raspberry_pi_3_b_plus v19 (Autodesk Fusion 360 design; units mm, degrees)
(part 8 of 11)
sketch "Sketch5" plane through (0, 0, 13.6) normal (0, 0, 1) x axis (-1, 0, 0)
  line L1 (-7.9893, 23.6893) -> (-7.9893, 10.7893)
  line L2 (-16.3393, 23.6893) -> (-7.9893, 23.6893)
  line L3 (-16.3393, 10.7893) -> (-16.3393, 23.6893)
  line L4 (-7.9893, 10.7893) -> (-16.3393, 10.7893)
  line L5 (-19.3393, 13.7893) -> (-16.3393, 10.7893)
  line L6 (-24.4893, 13.7893) -> (-19.3393, 13.7893)
  line L7 (-23.4893, 23.6893) -> (-23.4893, 22.3393)
  line L8 (0, 31.7433) -> (0, 0)
  line L9 (16.3393, 23.6893) -> (16.3393, 10.7893)
  line L10 (-24.4893, 22.3393) -> (-23.4893, 22.3393)
  line L11 (-24.4893, 13.7893) -> (-24.4893, 22.3393)
  line L12 (-22.3143, 26.1643) -> (-22.3143, 23.6893)
  line L13 (-20.9643, 23.8403) -> (-20.9643, 26.1643)
  line L14 (-16.5643, 23.8403) -> (-20.5643, 23.8403)
  line L15 (-16.5643, 23.6893) -> (-16.5643, 23.8403)
  line L16 (-22.3143, 23.6893) -> (-23.4893, 23.6893)
  line L17 (-16.3393, 23.6893) -> (-16.5643, 23.6893)
  line L18 (16.3393, 23.6893) -> (16.5643, 23.6893)
  line L19 (16.5643, 23.6893) -> (16.5643, 23.8403)
  line L20 (16.5643, 23.8403) -> (20.5643, 23.8403)
  line L21 (20.9643, 23.8403) -> (20.9643, 26.1643)
  line L22 (22.3143, 26.1643) -> (22.3143, 23.6893)
  line L23 (22.3143, 23.6893) -> (23.4893, 23.6893)
  line L24 (23.4893, 23.6893) -> (23.4893, 22.3393)
  line L25 (24.4893, 22.3393) -> (23.4893, 22.3393)
  line L26 (24.4893, 13.7893) -> (24.4893, 22.3393)
  line L27 (24.4893, 13.7893) -> (19.3393, 13.7893)
  line L28 (19.3393, 13.7893) -> (16.3393, 10.7893)
  arc A1 centre (-21.6393, 26.1643) radius 0.675 clockwise from (-22.3143, 26.1643) to (-20.9643, 26.1643)
  arc A2 centre (-20.7643, 23.8403) radius 0.2 clockwise from (-20.5643, 23.8403) to (-20.9643, 23.8403)
  arc A3 centre (20.7643, 23.8403) radius 0.2 clockwise from (20.9643, 23.8403) to (20.5643, 23.8403)
  arc A4 centre (21.6393, 26.1643) radius 0.675 clockwise from (20.9643, 26.1643) to (22.3143, 26.1643)
  point P5 (-16.3393, 10.7893)
  point P6 (-16.3393, 10.7893)
  point P4 (-16.3393, 23.6893)
  point P9 (-16.3393, 23.6893)
  point P1 (0, 0)
  point P10 (0, 0)
  point P22 (-21.6393, 26.8393)
  point P27 (-16.5643, 23.6893)
  point P44 (16.3393, 10.7893)
  point P7 (-19.3393, 13.7893)
  point P43 (19.3393, 13.7893)
  point P8 (-23.4893, 23.6893)
  point P39 (23.4893, 23.6893)
  point P29 (16.3393, 23.6893)
  point P14 (-23.4893, 22.3393)
  point P40 (23.4893, 22.3393)
  point P15 (-24.4893, 22.3393)
  point P41 (24.4893, 22.3393)
  point P16 (-24.4893, 13.7893)
  point P42 (24.4893, 13.7893)
  point P17 (-22.3143, 23.6893)
  point P38 (22.3143, 23.6893)
  point P18 (-22.3143, 26.1643)
  point P37 (22.3143, 26.1643)
  point P19 (-20.9643, 26.1643)
  point P35 (20.9643, 26.1643)
  point P21 (-20.9643, 23.8403)
  point P34 (20.9643, 23.8403)
  point P23 (-20.5643, 23.8403)
  point P32 (20.5643, 23.8403)
  point P25 (-20.5643, 23.8403)
  point P31 (20.5643, 23.8403)
  point P26 (-16.5643, 23.8403)
  point P30 (16.5643, 23.8403)
  point P28 (16.5643, 23.6893)
  point P24 (-20.7643, 23.8403)
  point P3 (-7.9893, 23.6893)
  point P20 (-21.6393, 26.1643)
  coincident P5 P6
  coincident P4 P9
  horizontal L16
  horizontal L6
  vertical L7
  coincident P1 P10
  vertical L8
  horizontal L10
  vertical L11
  tangent L12 A1
  vertical L13
  vertical L12
  tangent A1 L13
  midpoint A1 P22
  tangent L13 A2
  coincident P27 L16
  perpendicular L15 L16
  collinear L16 L17
  symmetric P6 L8 P44
  symmetric P7 L8 P43
  symmetric P8 L8 P39
  symmetric P9 L8 P29
  symmetric L8 P14 P40
  symmetric L8 P15 P41
  symmetric L8 P16 P42
  symmetric L8 P17 P38
  symmetric L8 P18 P37
  symmetric L8 P19 P35
  symmetric L8 A1 A4
  symmetric L8 P21 P34
  symmetric L8 P23 P32
  symmetric L8 A2 A3
  symmetric L8 P25 P31
  symmetric L8 P26 P30
  symmetric L8 P27 P28
  coincident P23 P25
  coincident P24 L14
  coincident P31 P32
  dimension "d32_6" angle L5 L6 = 45
  dimension "d33_6" distance L4 L6 = 3
  dimension "d46_5" distance L10 L16 = 1.35
  dimension "d47_4" distance L1 L11 = 16.5
  dimension "d54_7" radius A1 = 0.675 (= "1.35 mm / 2")
  dimension "d55_6" distance P22 L16 = 3.15 (= "3 mm + d1_5")
  dimension "d56_6" distance P3 P20 = 13.65 (= "10.75 mm + 3.05 mm - d1_5")
  dimension "d57_6" distance L7 L11 = 1
  dimension "d59_4" radius A2 = 0.2
  dimension "d60_4" distance L14 L16 = 0.151 (= "d1_5 + 0.001 mm")
  dimension "d145_2" distance P23 L15 = 4
extrude "Extrude4" add sketch "Sketch5" profile of L3 L5 L6 L7 L17 L9 L10 L11 L12 A1 L13 A2 L14 L15 L18 L19 L20 A3 L21 A4 L22 L23 L24 L25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 to an object
work_plane "WorkPlane2" AlongDistance -23.739 named "d150_1"
step "Refold1"
face "EdgeFlange7" FlangeHeight 0.25 named "d42_6" FlangeAngle 45 named "d43_5"
face "EdgeFlange8" FlangeHeight 4 named "d44_8" FlangeAngle 45 named "d45_5"
face "EdgeFlange10" FlangeHeight 1 named "d61_5" FlangeAngle 90 named "d62_4"
sketch "Sketch6" plane through (7.95, 0, 0) normal (1, 0, 0) x axis (0, 1, 0)
  line L1 (10.3, 13.1939) -> (10.3, 1.35)
  line L2 (7.45, 10.3439) -> (10.3, 13.1939)
  line L3 (7.45, 1.35) -> (7.45, 10.3439)
  line L4 (10.3, 1.35) -> (7.45, 1.35)
  line L5 (9.35, 3.65) -> (8.35, 3.65)
  line L6 (9.35, 2.5) -> (9.35, 3.65)
  line L7 (8.35, 2.5) -> (9.35, 2.5)
  line L8 (8.35, 3.65) -> (8.35, 2.5)
  point P6 (8.35, 3.65)
  point P7 (9.35, 3.65)
  point P9 (8.35, 2.5)
  point P1 (0, 0)
  point P8 (9.35, 2.5)
  point P10 (10.6, 1.35)
  horizontal L5
  vertical L6
  horizontal L7
  vertical L8
  dimension "d63_6" distance P6 P7 = 1
  dimension "d64_6" distance P6 P9 = 1.15
  dimension "d65_6" distance P1 P8 = 2.5
  dimension "d66_5" distance L6 P10 = 1.25
extrude "Extrude5" cut sketch "Sketch6" profile of L5 L6 L7 L8 no distance stored
face "EdgeFlange11" FlangeHeight 0.95 named "d68_6" FlangeAngle 10 named "d69_7" BendWidth 0.05 named "d70_3" BendDepth 0 named "d71_2" BendRemnant 0.3 named "d72_4"
work_plane "WorkPlane1" AlongDistance -10.45 (= "-( 10.75 mm - 2 * d1_5 )") named "d87_4"
sketch "Sketch2" plane through (0, -10.45, 0) normal (0, 1, 0) x axis (1, 0, 0)
  line L1 (7.8, -0.37) -> (-7.8, -0.37)
  line L2 (-6.915, -1.07) -> (-3.725, -1.07)
  line L3 (7.8, -13.37) -> (7.8, -0.37)
  line L4 (5.95, -10.87) -> (-5.95, -10.87)
  line L5 (5.95, -8.37) -> (5.95, -10.87)
  line L6 (-6.915, -3.33) -> (-6.915, -1.07)
  line L7 (-3.725, -3.33) -> (-6.915, -3.33)
  line L8 (6.95, -8.37) -> (5.95, -8.37)
  line L9 (-7.8, -0.37) -> (-7.8, -13.37)
  line L10 (-7.8, -13.37) -> (7.8, -13.37)
  line L11 (-3.725, -3.33) -> (-3.725, -1.07)
  line L12 (2.03, -0.97) -> (2.03, -2.31)
  line L13 (3.725, -3.33) -> (3.725, -1.07)
  line L14 (-3.15, -0.97) -> (3.15, -0.97)
  line L15 (6.95, -5.37) -> (6.95, -8.37)
  line L16 (-6.95, -8.37) -> (-6.95, -5.37)
  line L17 (3.725, -1.07) -> (6.915, -1.07)
  line L18 (5.955, -5.37) -> (6.95, -5.37)
  line L19 (-6.95, -5.37) -> (-5.955, -5.37)
  line L20 (-5.95, -8.37) -> (-6.95, -8.37)
  line L21 (6.915, -3.33) -> (3.725, -3.33)
  line L22 (-5.95, -10.87) -> (-5.95, -8.37)
  line L23 (6.915, -1.07) -> (6.915, -3.33)
  line L24 (-2.03, -2.31) -> (-2.03, -0.97)
  line L25 (0, -15.0494) -> (0, 0)
  line L26 (-5.955, -4.13) -> (-5.955, -5.37)
  line L27 (-5.955, -4.13) -> (-3.15, -4.13)
  line L28 (-3.15, -0.97) -> (-3.15, -4.13)
  line L29 (-3.15, -2.31) -> (-2.03, -2.31)
  line L30 (5.955, -4.13) -> (5.955, -5.37)
  line L31 (3.15, -4.13) -> (5.955, -4.13)
  line L32 (3.15, -0.97) -> (3.15, -4.13)
  line L33 (2.03, -2.31) -> (3.15, -2.31)
  line L34 (-5.955, -5.37) -> (-5.95, -8.37)
  line L35 (5.955, -5.37) -> (5.95, -8.37)
  line L36 (5.9525, -6.87) -> (-5.9525, -6.87)
  line L37 (-6.915, -1.07) -> (-3.725, -3.33)
  line L38 (-3.725, -1.07) -> (-6.915, -3.33)
  line L39 (3.725, -1.07) -> (6.915, -3.33)
  line L40 (6.915, -1.07) -> (3.725, -3.33)
  point P1 (0, 0)
  point P26 (0, 0)
  point P20 (-7.8, -0.37)
  point P23 (7.8, -0.37)
  point P5 (-5.95, -10.87)
  point P6 (5.95, -10.87)
  point P28 (-6.95, -6.87)
  point P8 (-6.95, -8.37)
  point P17 (6.95, -8.37)
  point P3 (-6.95, -5.37)
  point P18 (6.95, -5.37)
  point P12 (-2.03, -2.31)
  point P34 (-2.03, -2.31)
  point P16 (2.03, -2.31)
  point P30 (2.03, -2.31)
  point P33 (3.15, -4.13)
  point P36 (-3.15, -4.13)
  point P29 (5.955, -5.37)
  point P38 (-5.955, -5.37)
  point P10 (6.915, -3.33)
  point P19 (-6.915, -3.33)
  point P15 (3.725, -1.07)
  point P24 (-3.725, -1.07)
  point P37 (-3.15, -2.31)
  point P11 (-2.03, -0.97)
  point P14 (2.03, -0.97)
  point P35 (3.15, -2.31)
  point P41 (-5.9525, -6.87)
  point P42 (5.9525, -6.87)
  point P43 (-5.32, -2.2)
  point P44 (5.32, -2.2)
  horizontal L1
  vertical L3
  vertical L9
  horizontal L10
  horizontal L4
  coincident P1 P26
  vertical L25
  symmetric P20 P23 L25
  vertical L5
  vertical L22
  vertical L6
  vertical L23
  vertical L12
  vertical L24
  vertical L15
  horizontal L21
  horizontal L7
  horizontal L17
  horizontal L2
  symmetric P5 P6 L25
  midpoint L16 P28
  symmetric P8 P17 L25
  symmetric P3 P18 L25
  horizontal L19
  horizontal L20
  coincident P12 P34
  horizontal L29
  vertical L28
  horizontal L27
  vertical L26
  coincident P16 P30
  horizontal L33
  vertical L32
  horizontal L31
  vertical L30
  horizontal L18
  symmetric P12 P16 L25
  symmetric L25 P33 P36
  symmetric L25 P29 P38
  symmetric P10 P19 L25
  vertical L13
  symmetric P15 P24 L25
  horizontal L8
  coincident P37 L28
  coincident P11 L14
  coincident P14 L14
  coincident P35 L32
  midpoint L34 P41
  midpoint L35 P42
  midpoint L37 P43
  midpoint L40 P44
  dimension "d88_3" distance P1 L1 = 0.37
  dimension "d89_6" distance L1 L10 = 13
  dimension "d90_4" distance L3 L9 = 15.6
  dimension "d92_6" distance L4 L10 = 2.5
  dimension "d93_4" distance L9 L22 = 1.85
  dimension "d94_4" distance L16 L22 = 1
  dimension "d95_2" distance L1 P28 = 6.5
  dimension "d103_4" distance P29 P38 = 11.91
  dimension "d104_4" distance L28 L32 = 6.3
  dimension "d105_3" distance L12 L24 = 4.06
  dimension "d106_2" distance L2 L7 = 2.26
  dimension "d107_4" distance L6 L11 = 3.19
  dimension "d108_4" distance L1 L2 = 0.7
  dimension "d110_2" distance L1 L14 = 0.6
  dimension "d111_4" distance L14 L19 = 4.4
  dimension "d112_4" distance L14 L29 = 1.34
  dimension "d113_4" distance L14 L27 = 3.16
  dimension "d274_5" distance P43 P44 = 10.64
extrude "Extrude1" new body sketch "Sketch2" profile of L1 L2 L3 L4 L5 L6 L7 L8 L9 L10 L11 L12 L13 L14 L15 L16 L17 L18 L19 L20 L21 L22 L23 L24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 along normal blind 20.75 named "d114_4"
extrude "Extrude2" cut sketch "Sketch2" profile of L2 L4 L5 L6 L7 L8 L11 L12 L13 L14 L15 L16 L17 L18 L19 L20 L21 L22 L23 L24 L26 L27 L28 L29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 along normal blind 9.5 named "d116_2"
extrude "Extrude12" cut sketch "Sketch2" profile of L8 L12 L14 L15 L16 L18 L19 L20 L24 L26 L27 L28 L29 L30 L31 L32 L33 L34 L35 L36 along normal blind 11 named "d266_5"
chamfer "Chamfer5" distance 1.5 named "d268_5" Rotate Angle 20 named "d269_5"
extrude "Extrude11" add sketch "Sketch2" profile of L12 L14 L24 L28 L29 L32 L33 along normal blind 1.5 named "d262_3"
sketch "Sketch3" plane through (0, 10.3, 0) normal (0, 1, 0) x axis (-1, 0, 0)
  line L1 (-7.8, 0.37) -> (-7.8, 13.37)
  line L2 (7.8, 0.37) -> (-7.8, 0.37)
  line L3 (7.8, 13.37) -> (7.8, 0.37)
  line L4 (-7.8, 13.37) -> (7.8, 13.37)
  line L5 (6.95, 12.67) -> (-6.95, 12.67)
  line L6 (-7.6, 0.37) -> (-7.6, 13.37)
  line L7 (0, 14.7885) -> (0, 0)
  line L8 (7.6, 0.37) -> (7.6, 13.37)
  line L9 (-6.75, 11.77) -> (-6.75, 12.67)
  line L10 (-4.4, 11.77) -> (-6.75, 11.77)
  line L11 (-4.4, 10.87) -> (-4.4, 11.77)
  line L12 (5.75, 10.87) -> (-5.75, 10.87)
  line L13 (4.4, 11.77) -> (4.4, 10.87)
  line L14 (6.75, 11.77) -> (4.4, 11.77)
  line L15 (6.75, 12.67) -> (6.75, 11.77)
  line L16 (-5.75, 10.87) -> (-5.75, 11.77)
  line L17 (5.75, 10.87) -> (5.75, 11.77)
  line L18 (-6.45, 1.37) -> (-6.95, 1.37)
  line L19 (-6.45, 0.87) -> (-6.45, 1.37)
  line L20 (-6.95, 0.87) -> (-6.45, 0.87)
  line L21 (-6.95, 0.87) -> (-6.95, 0.37)
  line L22 (-6.95, 12.67) -> (-6.95, 1.37)
  line L23 (6.45, 1.37) -> (6.95, 1.37)
  line L24 (6.45, 0.87) -> (6.45, 1.37)
  line L25 (6.95, 0.87) -> (6.45, 0.87)
  line L26 (6.95, 1.37) -> (6.95, 12.67)
  line L27 (6.95, 0.37) -> (6.95, 0.87)
  point P10 (-7.6, 13.37)
  point P11 (-7.6, 0.37)
  point P9 (-6.95, 0.37)
  point P8 (6.95, 0.37)
  point P1 (0, 0)
  point P12 (0, 0)
  point P6 (-6.95, 12.67)
  point P7 (6.95, 12.67)
  point P14 (7.6, 13.37)
  point P15 (7.6, 0.37)
  point P16 (-6.75, 12.67)
  point P23 (6.75, 12.67)
  point P18 (-4.4, 11.77)
  point P21 (4.4, 11.77)
  point P17 (-6.75, 11.77)
  point P22 (6.75, 11.77)
  point P24 (-5.75, 11.77)
  point P26 (5.75, 11.77)
  point P20 (4.4, 10.87)
  point P27 (5.75, 10.87)
  point P28 (5.75, 10.87)
  point P19 (-4.4, 10.87)
  point P25 (-5.75, 10.87)
  point P29 (-5.75, 10.87)
  point P30 (-6.95, 1.37)
  point P37 (6.95, 0.87)
  point P31 (-6.45, 1.37)
  point P35 (6.45, 1.37)
  point P32 (-6.45, 0.87)
  point P36 (6.45, 0.87)
  perpendicular L5 L26
  parallel L21 L26
  horizontal L5
  coincident L4 P10
  coincident L2 P11
  vertical L6
  coincident L2 P9
  coincident L2 P8
  coincident P1 P12
  vertical L7
  symmetric P6 P7 L7
  coincident L4 P14
  coincident L2 P15
  vertical L8
  symmetric P10 L7 P14
  coincident L5 P16
  coincident L5 P23
  vertical L13
  vertical L15
  horizontal L12
  vertical L11
  horizontal L10
  vertical L9
  horizontal L14
  symmetric L7 P18 P21
  symmetric L7 P17 P22
  coincident L10 P24
  coincident L14 P26
  coincident P20 L12
  coincident P27 P28
  vertical L17
  vertical L16
  coincident P19 L12
  coincident P25 P29
  symmetric L7 P25 P27
  coincident P30 L21
  horizontal L18
  vertical L19
  horizontal L20
  collinear L21 L22
  coincident P37 L26
  horizontal L25
  vertical L24
  horizontal L23
  symmetric L7 P31 P35
  symmetric L7 P32 P36
  collinear L26 L27
  dimension "d118_2" distance L4 L5 = 0.7
  dimension "d119_1" distance L1 L6 = 0.2
  dimension "d120_3" distance L6 L21 = 0.65
  dimension "d128_4" distance L5 L12 = 1.8
  dimension "d129_4" distance P16 P23 = 13.5
  dimension "d130_4" distance L5 L10 = 0.9
  dimension "d131_4" distance L11 L13 = 8.8
  dimension "d132_2" distance L16 L17 = 11.5
  dimension "d358_3" distance L18 L20 = 0.5
  dimension "d359_3" distance P9 L20 = 0.5
  dimension "d360_3" distance L19 L22 = 0.5
extrude "Extrude3" cut sketch "Sketch3" profile of L2 L5 L27 L22 L9 L10 L11 L12 L13 L14 L15 L16 L17 L18 L19 L20 L23 L24 L25 against normal blind 8.75 named "d121_1"
extrude "Extrude4" cut sketch "Sketch3" profile of L1 L2 L3 L4 L6 L8 against normal blind 4.5 named "d123_3"
extrude "Extrude6" cut sketch "Sketch3" profile of L5 L9 L10 L11 L12 L13 L14 L15 L16 L17 against normal blind 19 named "d133_4"
chamfer "Chamfer2" distance 0.25 named "d139_2"
sketch "Sketch4" plane through (0, 0, 10.87) normal (0, 0, 1) x axis (-1, 0, 0)
  line L1 (5.75, -1.55) -> (-5.75, -1.55)
  line L2 (5.75, 0.95) -> (5.75, -1.55)
  line L3 (-5.75, 0.95) -> (5.75, 0.95)
  line L4 (-5.75, -1.55) -> (-5.75, 0.95)
  line L5 (0.76, 0.95) -> (0.76, -1.55)
  line L6 (0.26, 0.95) -> (0.26, -1.55)
  line L7 (3.82, 0.95) -> (3.82, -1.55)
  line L8 (3.32, 0.95) -> (3.32, -1.55)
  line L9 (2.8, 0.95) -> (2.8, -1.55)
  line L10 (2.3, 0.95) -> (2.3, -1.55)
  line L11 (1.78, 0.95) -> (1.78, -1.55)
  line L12 (1.28, 0.95) -> (1.28, -1.55)
  line L13 (-0.26, 0.95) -> (-0.26, -1.55)
  line L14 (-0.76, 0.95) -> (-0.76, -1.55)
  line L15 (-1.28, 0.95) -> (-1.28, -1.55)
  line L16 (-1.78, 0.95) -> (-1.78, -1.55)
  line L17 (-2.3, 0.95) -> (-2.3, -1.55)
  line L18 (-2.8, 0.95) -> (-2.8, -1.55)
  line L19 (-3.32, 0.95) -> (-3.32, -1.55)
  line L20 (-3.82, 0.95) -> (-3.82, -1.55)
  point P7 (0.76, 0.95)
  point P8 (0.26, -1.55)
  point P9 (0.26, 0.95)
  point P6 (0.76, -1.55)
  point P1 (0, 0)
  coincident L3 P7
  coincident L1 P8
  coincident L3 P9
  vertical L5
  vertical L6
  coincident L1 P6
  dimension "d170_4" distance L5 L6 = 0.5
  dimension "d171_2" distance P1 L5 = 0.76 (= "( d170_4 + d168_3 ) / 2")
  dimension "d168_3" R-Pattern1-uDistance = 1.02
  dimension "d169_3" R-Pattern1-vDistance = 0
extrude "Extrude8" cut sketch "Sketch4" profile of L1 L3 L5 L6 L7 L8 L9 L10 L11 L12 L13 L14 L15 L16 L17 L18 L19 L20 against normal blind 2.5 named "d172_2"
draft "Draft1" Angle1 -20 named "d174_2" Angle2 0 named "d175_3"
position "Position3"
sketch "Sketch1" plane through (0, 0, 0) normal (0, 0, 1) x axis (1, 0, 0)
  line L1 (-1, -9) -> (1, -9)
  line L2 (0, -8.1439) -> (0, -9)
  line L3 (-0.6379, -9) -> (0.0615, -7.5)
  line L4 (-0.9, -7.5) -> (-1, -7.5)
  line L5 (0.9, -7.5) -> (0.9, -7)
  line L6 (-1, -7.5) -> (-1, -9)
  line L7 (-0.1532, -8.907) -> (0, -8.907)
  line L8 (0.1995, -7.5) -> (-0.5, -9)
  line L9 (-0.1532, -8.975) -> (0, -8.975)
  line L10 (-0.4, -7.5) -> (-0.4, -7)
  line L11 (0.4, -7) -> (0.4, -7.5)
  line L12 (0.4, -7.5) -> (-0.4, -7.5)
  line L13 (1, -7.5) -> (0.9, -7.5)
  line L14 (-0.9, -7) -> (-0.9, -7.5)
  line L15 (1, -9) -> (1, -7.5)
  line L16 (1.2681, -6.5607) -> (0.984, -6.8131)
  line L17 (0.6519, -6.4393) -> (0.936, -6.1869)
  line L18 (1.02, -5) -> (1.02, -6)
  line L19 (1.52, -5) -> (1.02, -5)
  line L20 (1.52, -6) -> (1.52, -5)
  line L21 (-1.52, -5) -> (-1.02, -5)
  line L22 (-1.02, -5) -> (-1.02, -6)
  line L23 (-0.6519, -6.4393) -> (-0.936, -6.1869)
  line L24 (-1.2681, -6.5607) -> (-0.984, -6.8131)
  line L25 (-1.52, -6) -> (-1.52, -5)
  arc A1 centre (-0.1532, -9.175) radius 0.268 clockwise from (-0.3562, -9) to (-0.1532, -8.907)
  arc A2 centre (-0.1532, -9.175) radius 0.2 clockwise from (-0.25, -9) to (-0.1532, -8.975)
  arc A3 centre (1.15, -7) radius 0.25 clockwise from (0.9, -7) to (0.984, -6.8131)
  arc A4 centre (1.15, -7) radius 0.75 clockwise from (0.4, -7) to (0.6519, -6.4393)
  arc A5 centre (0.77, -6) radius 0.25 clockwise from (1.02, -6) to (0.936, -6.1869)
  arc A6 centre (0.77, -6) radius 0.75 clockwise from (1.52, -6) to (1.2681, -6.5607)
  arc A7 centre (-0.77, -6) radius 0.25 clockwise from (-0.936, -6.1869) to (-1.02, -6)
  arc A8 centre (-1.15, -7) radius 0.75 clockwise from (-0.6519, -6.4393) to (-0.4, -7)
  arc A9 centre (-1.15, -7) radius 0.25 clockwise from (-0.984, -6.8131) to (-0.9, -7)
  arc A10 centre (-0.77, -6) radius 0.75 clockwise from (-1.2681, -6.5607) to (-1.52, -6)
  point P2 (1, -9)
  point P9 (1, -9)
  point P3 (-1, -9)
  point P6 (-1, -9)
  point P21 (0, -8.975)
  point P30 (0, -8.907)
  point P16 (-0.25, -9)
  point P15 (-0.3562, -9)
  point P23 (-0.5, -9)
  point P10 (-0.6379, -9)
  point P25 (0.0615, -7.5)
  point P19 (0.1995, -7.5)
  point P4 (0, -9)
  point P17 (0, -9)
  point P7 (0.9, -7)
  point P26 (-0.9, -7)
  point P8 (0.4, -7)
  point P22 (-0.4, -7)
  point P1 (0, 0)
  point P53 (-0.9, -7)
  point P50 (-0.4, -7)
  point P31 (0.984, -6.8131)
  point P52 (-0.984, -6.8131)
  point P33 (1.2681, -6.5607)
  point P54 (-1.2681, -6.5607)
  point P34 (0.936, -6.1869)
  point P47 (-0.936, -6.1869)
  point P35 (0.6519, -6.4393)
  point P48 (-0.6519, -6.4393)
  point P37 (1.02, -6)
  point P45 (-1.02, -6)
  point P39 (1.02, -5)
  point P43 (-1.02, -5)
  point P40 (1.52, -5)
  point P44 (-1.52, -5)
  point P41 (1.52, -6)
  point P56 (-1.52, -6)
  point P57 (-1.27, -5)
  point P58 (1.27, -5)
  point P27 (1, -7.5)
  point P24 (0.9, -7.5)
  horizontal L1
  vertical L2
  symmetric P2 L1 P9
  symmetric P3 L1 P6
  coincident L2 P21
  coincident L2 P30
  coincident L1 P16
  coincident L1 P15
  coincident L1 P23
  coincident L1 P10
  coincident P25 L12
  coincident P19 L12
  coincident P3 P6
  coincident P2 P9
  midpoint L1 P4
  coincident L1 P17
  coincident P4 P17
  parallel L3 L8
  horizontal L12
  collinear L12 L13
  collinear L4 L12
  vertical L15
  vertical L6
  vertical L10
  vertical L14
  vertical L11
  vertical L5
  symmetric L2 P7 P26
  symmetric L2 P8 P22
  tangent L7 A1
  tangent L9 A2
  concentric A1 A2
  coincident P1 L2
  tangent L5 A3
  tangent A3 L16
  tangent L17 A4
  tangent L11 A4
  tangent L17 A5
  tangent A5 L18
  tangent L20 A6
  tangent L16 A6
  vertical L20
  horizontal L19
  vertical L18
  concentric A5 A6
  concentric A3 A4
  parallel L16 L17
  equal A4 A6
  symmetric L2 P7 P53
  symmetric L2 P8 P50
  symmetric L2 P31 P52
  symmetric L2 A3 A9
  symmetric L2 P33 P54
  symmetric L2 P34 P47
  symmetric L2 P35 P48
  symmetric L2 A4 A8
  symmetric L2 P37 P45
  symmetric L2 A5 A7
  symmetric L2 P39 P43
  symmetric L2 P40 P44
  symmetric L2 P41 P56
  symmetric L2 A6 A10
  midpoint L21 P57
  midpoint L19 P58
  dimension "d179_3" distance P2 P3 = 2
  dimension "d212_2" angle L1 L8 = 65
  dimension "d213_2" distance L5 L11 = 0.5
  dimension "d216_1" distance L7 L9 = 0.068
  dimension "d217_3" distance L1 L9 = 0.025
  dimension "d218_4" distance L2 P16 = 0.25 (= "d191_3 / 2")
  dimension "d219_3" radius A2 = 0.2
  dimension "d220_3" distance L2 P23 = 0.5 (= "d191_3")
  dimension "d221_3" distance L3 L8 = 0.125
  dimension "d222_3" distance P9 P27 = 1.5
  dimension "d223_4" distance P7 P24 = 0.5
  dimension "d225_4" distance P1 L1 = 9
  dimension "d257_1" radius A4 = 0.75
  dimension "d258_2" distance P57 P58 = 2.54
  dimension "d259_2" distance L5 L15 = 0.1
  dimension "d260_4" distance L1 L19 = 4
  dimension "d261_3" distance P7 P41 = 1
extrude "Extrude1" new body sketch "Sketch1" distance 0.5 named "d191_3"
revolve "Revolve1" sketch "Sketch1" AlongAngle 360 named "d193_4"
revolve "Revolve2" sketch "Sketch1" AlongAngle 360 named "d194_3"
sketch "Sketch2" plane through (0, 0, 0) normal (0, 0, 1) x axis (1, 0, 0)
  line L1 (-1.53, -10) -> (1.53, -10)
  line L2 (-1.53, -6.25) -> (-1.53, -10)
  line L3 (1.53, -6.25) -> (-1.53, -6.25)
  line L4 (1.53, -10) -> (1.53, -6.25)
  line L5 (-1.53, -6.25) -> (1.53, -10)
  line L6 (1.53, -6.25) -> (-1.53, -10)
  line L7 (0, -8.1439) -> (0, -9)
  line L8 (-1, -9) -> (1, -9)
  arc A1 centre (0, -7.4195) radius 3 clockwise from (1.53, -10) to (-1.53, -10)
  point P6 (0, -8.125)
  perpendicular L1 L2
  parallel L1 L3
  parallel L2 L4
  horizontal L1
  coincident L5 P6
  coincident L6 P6
  coincident P6 L7
  dimension "d226_3" distance L2 L4 = 3.06
  dimension "d227_4" distance L3 L8 = 2.75
  dimension "d228_4" distance L1 L8 = 1
  dimension "d229_4" radius A1 = 3
sketch "Sketch3" plane through (-1.52, 0, 0) normal (-1, 0, 0) x axis (0, -1, 0)
  line L1 (4.31, -4.5) -> (4.31, -0.94)
  line L2 (3.81, -4.5) -> (4.31, -4.5)
  line L3 (3.81, -0.94) -> (3.81, -4.5)
  line L4 (6, 0.25) -> (6, -0.25)
  line L5 (5, 0.25) -> (6, 0.25)
  line L6 (5, -0.25) -> (5, 0.25)
  line L7 (6, -0.25) -> (5, -0.25)
  arc A1 centre (5, -0.94) radius 0.69 clockwise from (4.31, -0.94) to (5, -0.25)
  arc A2 centre (5, -0.94) radius 1.19 clockwise from (3.81, -0.94) to (5, 0.25)
  point P6 (4.06, -4.5)
  point P12 (5, -0.25)
  point P13 (5, -0.25)
  point P11 (5, 0.25)
  point P14 (5, 0.25)
  point P1 (0, 0)
  vertical L1
  vertical L3
  horizontal L2
  midpoint L2 P6
  tangent L1 A1
  tangent L3 A2
  concentric A1 A2
  coincident P12 P13
  coincident P11 P14
  tangent A2 L5
  dimension "d230_3" distance P1 P6 = 4.06
  dimension "d231_3" distance P1 L2 = 4.5
extrude "Extrude3" add sketch "Sketch3" profile of L1 L2 L3 A1 A2 L6 to an object
extrude "Extrude4" sketch "Sketch3" profile of L1 L2 L3 A1 A2 L6 to an object
copy_paste "CopyPaste1"
position "Position4"
extrude "Extrude1" new body sketch "Sketch2" profile of L2 L3 L4 A1 distance 2.2 named "d237_4"
extrude "Extrude2" new body sketch "Sketch2" profile of L2 L3 L4 A1 distance 2.2 named "d239_2"
sketch "Sketch5" plane through (0, 0, 0.37) normal (0, 0, -1) x axis (1, 0, 0)
  line L1 (7.8, -5.8) -> (7.6, -5.8)
  line L2 (-6.95, -1.55) -> (-6.95, -10.3)
  line L3 (6.95, -1.55) -> (-6.95, -1.55)
  line L4 (6.95, -10.3) -> (6.95, -1.55)
  line L5 (7.8, 10.45) -> (7.8, -5.8)
  line L6 (-7.8, 10.45) -> (7.8, 10.45)
  line L7 (-7.8, -5.8) -> (-7.8, 10.45)
  line L8 (0, 4.4388) -> (0, 0)
  line L9 (4.375, 3.8) -> (4.375, 10.45)
  line L10 (3.825, 3.8) -> (4.375, 3.8)
  line L11 (3.825, 4.32) -> (3.825, 3.8)
  line L12 (3.895, 4.32) -> (3.825, 4.32)
  line L13 (3.895, 4.82) -> (3.895, 4.32)
  line L14 (3.725, 5.1144) -> (3.895, 4.82)
  line L15 (3.725, 10.45) -> (3.725, 5.1144)
  line L16 (6.915, 3.8) -> (6.915, 10.45)
  line L17 (6.365, 3.8) -> (6.915, 3.8)
  line L18 (6.365, 4.32) -> (6.365, 3.8)
  line L19 (6.435, 4.32) -> (6.365, 4.32)
  line L20 (6.435, 4.82) -> (6.435, 4.32)
  line L21 (6.265, 5.1144) -> (6.435, 4.82)
  line L22 (6.265, 10.45) -> (6.265, 5.1144)
  line L23 (-6.915, 3.8) -> (-6.915, 10.45)
  line L24 (-6.365, 3.8) -> (-6.915, 3.8)
  line L25 (-6.365, 4.32) -> (-6.365, 3.8)
  line L26 (-6.435, 4.32) -> (-6.365, 4.32)
  line L27 (-6.435, 4.82) -> (-6.435, 4.32)
  line L28 (-6.265, 5.1144) -> (-6.435, 4.82)
  line L29 (-6.265, 10.45) -> (-6.265, 5.1144)
  line L30 (-4.375, 3.8) -> (-4.375, 10.45)
  line L31 (-3.825, 3.8) -> (-4.375, 3.8)
  line L32 (-3.825, 4.32) -> (-3.825, 3.8)
  line L33 (-3.895, 4.32) -> (-3.825, 4.32)
  line L34 (-3.895, 4.82) -> (-3.895, 4.32)
  line L35 (-3.725, 5.1144) -> (-3.895, 4.82)
  line L36 (-3.725, 10.45) -> (-3.725, 5.1144)
  line L37 (-7.6, -10.3) -> (-7.6, -5.8)
  line L38 (-6.95, -10.3) -> (-7.6, -10.3)
  line L39 (7.6, -10.3) -> (6.95, -10.3)
  line L40 (7.6, -5.8) -> (7.6, -10.3)
  line L41 (-7.6, -5.8) -> (-7.8, -5.8)
  circle C1 centre (-5.715, 0) radius 1.6
  arc A1 centre (-4.023, 1.692) radius 1.324 clockwise from (-4.1596, 0.375) to (-5.34, 1.5554)
  arc A2 centre (-7.407, 1.692) radius 1.324 clockwise from (-6.09, 1.5554) to (-7.2704, 0.375)
  arc A3 centre (-7.407, -1.692) radius 1.324 clockwise from (-7.2704, -0.375) to (-6.09, -1.5554)
  arc A4 centre (-4.023, -1.692) radius 1.324 clockwise from (-5.34, -1.5554) to (-4.1596, -0.375)
  circle C2 centre (5.715, 0) radius 1.6
  arc A5 centre (7.407, 1.692) radius 1.324 clockwise from (7.2704, 0.375) to (6.09, 1.5554)
  arc A6 centre (4.023, 1.692) radius 1.324 clockwise from (5.34, 1.5554) to (4.1596, 0.375)
  arc A7 centre (4.023, -1.692) radius 1.324 clockwise from (4.1596, -0.375) to (5.34, -1.5554)
  arc A8 centre (7.407, -1.692) radius 1.324 clockwise from (6.09, -1.5554) to (7.2704, -0.375)
  point P12 (-4.1596, 0.375)
  point P11 (-5.34, 1.5554)
  point P13 (-4.023, 1.692)
  point P20 (-4.023, -1.692)
  point P1 (0, 0)
  point P24 (0, 0)
  point P31 (5.34, 1.5554)
  point P32 (4.1596, 0.375)
  point P15 (-7.2704, 0.375)
  point P28 (7.2704, 0.375)
  point P16 (-6.09, 1.5554)
  point P29 (6.09, 1.5554)
  point P18 (-6.09, -1.5554)
  point P37 (6.09, -1.5554)
  point P19 (-7.2704, -0.375)
  point P38 (7.2704, -0.375)
  point P21 (-4.1596, -0.375)
  point P34 (4.1596, -0.375)
  point P22 (-5.34, -1.5554)
  point P35 (5.34, -1.5554)
  point P39 (4.375, 10.45)
  point P46 (3.725, 10.45)
  point P47 (3.825, 4.06)
  point P64 (-4.375, 10.45)
  point P40 (4.375, 3.8)
  point P65 (-4.375, 3.8)
  point P41 (3.825, 3.8)
  point P66 (-3.825, 3.8)
  point P42 (3.825, 4.32)
  point P67 (-3.825, 4.32)
  point P43 (3.895, 4.32)
  point P68 (-3.895, 4.32)
  point P44 (3.895, 4.82)
  point P69 (-3.895, 4.82)
  point P45 (3.725, 5.1144)
  point P70 (-3.725, 5.1144)
  point P71 (-3.725, 10.45)
  point P48 (6.915, 10.45)
  point P56 (-6.915, 10.45)
  point P49 (6.915, 3.8)
  point P57 (-6.915, 3.8)
  point P50 (6.365, 3.8)
  point P58 (-6.365, 3.8)
  point P51 (6.365, 4.32)
  point P59 (-6.365, 4.32)
  point P52 (6.435, 4.32)
  point P60 (-6.435, 4.32)
  point P53 (6.435, 4.82)
  point P61 (-6.435, 4.82)
  point P54 (6.265, 5.1144)
  point P62 (-6.265, 5.1144)
  point P55 (6.265, 10.45)
  point P63 (-6.265, 10.45)
  point P72 (4.1, 3.8)
  point P73 (-4.1, 3.8)
  point P10 (-5.715, 0)
  point P23 (-7.65, 10.75)
  point P26 (5.715, 0)
  coincident C1 P12
  coincident C1 P11
  vertical P13 P20
  coincident P1 P24
  vertical L8
  symmetric C1 L8 C2
  symmetric P11 L8 P31
  symmetric P12 L8 P32
  symmetric A1 L8 A6
  symmetric P15 L8 P28
  symmetric P16 L8 P29
  symmetric A2 L8 A5
  symmetric P18 L8 P37
  symmetric P19 L8 P38
  symmetric A3 L8 A8
  symmetric P21 L8 P34
  symmetric P22 L8 P35
  symmetric A4 L8 A7
  coincident L6 P39
  vertical L13
  coincident L6 P46
  vertical L15
  vertical L9
  horizontal L10
  vertical L11
  horizontal L12
  midpoint L11 P47
  symmetric L8 P39 P64
  symmetric L8 P40 P65
  symmetric L8 P41 P66
  symmetric L8 P42 P67
  symmetric L8 P43 P68
  symmetric L8 P44 P69
  symmetric L8 P45 P70
  symmetric L8 P46 P71
  symmetric L8 P48 P56
  symmetric L8 P49 P57
  symmetric L8 P50 P58
  symmetric L8 P51 P59
  symmetric L8 P52 P60
  symmetric L8 P53 P61
  symmetric L8 P54 P62
  symmetric L8 P55 P63
  midpoint L10 P72
  midpoint L31 P73
  dimension "d202" diameter C1 = 3.2
  dimension "d205_1" distance P12 P21 = 0.75
  dimension "d206_2" radius A1 = 1.324
  dimension "d207_1" distance P10 P23 = 10.75
  dimension "d208_4" distance P10 P26 = 11.43
  dimension "d242_4" distance L9 L13 = 0.48
  dimension "d244_4" distance L10 L12 = 0.52
  dimension "d245_4" distance P43 P44 = 0.5
  dimension "d246_2" distance P1 P47 = 4.06
  dimension "d252_2" angle L13 L14 = 30
  dimension "d271_5" distance L9 L15 = 0.65
  dimension "d272_5" distance L9 L11 = 0.55
  dimension "d273_5" distance P72 P73 = 8.2
  dimension "d204_2" C-Pattern1-Angle = 360
  dimension "d249_1" R-Pattern1-uDistance = 2.54
  dimension "d250_2" R-Pattern1-vDistance = 0
extrude "Extrude9" add sketch "Sketch5" profile of C1 A1 A2 A3 A4 C2 A5 A6 A7 A8 along normal blind 3.5 named "d210_2"
sketch "Sketch1" plane through (0, 0, 0) normal (1, 0, 0) x axis (0, 1, 0)
  line L1 (-7, 11.8) -> (-3.6279, 11.4913)
  line L2 (-7.7223, 10.8892) -> (-0.2048, 8.153)
  line L3 (5, 11.4913) -> (5, 11.8413)
  line L4 (-3.6279, 11.4913) -> (5, 11.4913)
  line L5 (5, 11.8413) -> (-3.612, 11.8413)
  line L6 (-6.984, 12.15) -> (-7.5, 12.15)
  line L7 (-0.0851, 8.4819) -> (-7.6026, 11.2181)
  line L8 (-7.5, 11.8) -> (-7, 11.8)
  line L9 (-3.612, 11.8413) -> (-6.984, 12.15)
  line L10 (-0.2048, 8.153) -> (-0.0851, 8.4819)
  arc A1 centre (-7.5, 11.5) radius 0.3 clockwise from (-7.6026, 11.2181) to (-7.5, 11.8)
  arc A2 centre (-7.5, 11.5) radius 0.65 clockwise from (-7.7223, 10.8892) to (-7.5, 12.15)
  point P4 (-7.5, 11.8)
  point P16 (-7.5, 11.8)
  point P2 (-7.5, 12.15)
  point P9 (-7.5, 12.15)
  point P5 (-7, 11.8)
  point P11 (-3.6279, 11.4913)
  point P1 (0, 0)
  point P8 (-7.5, 11.5)
  horizontal L4
  vertical L3
  horizontal L5
  horizontal L8
  horizontal L6
  perpendicular L2 L10
  tangent A1 L7
  coincident P4 P16
  tangent A1 L8
  coincident P2 P9
  tangent L2 A2
  parallel L1 L9
  tangent A2 L6
  dimension "d73_6" angle L7 L8 = 20
  dimension "d74_6" distance L2 L7 = 0.35
  dimension "d75_5" angle L1 L8 = 5.23
  dimension "d76_4" distance P5 P11 = 3.3721
  dimension "d77_4" distance L4 L5 = 0.35
  dimension "d78_4" distance L1 L9 = 0.35 (= "d77_4")
  dimension "d80_5" distance P1 P16 = 7.5
  dimension "d81_5" distance P5 P16 = 0.5
  dimension "d82_6" distance P1 L6 = 12.15 (= "12.5 mm - ( 0.35 ) * 1 mm")
  dimension "d84_2" radius A1 = 0.3
  dimension "d85_1" distance P8 L10 = 8
  dimension "d86_5" distance P1 L3 = 5
extrude "Extrude1" new body sketch "Sketch1" distance 0.5 named "d276_5" from offset -0.51 (= "-( 1.02 / 2 ) * 1 mm") named "d275_5"
extrude "Extrude10" cut sketch "Sketch5" profile of L6 L9 L10 L11 L12 L13 L14 L15 L16 L17 L18 L19 L20 L21 L22 L23 L24 L25 L26 L27 L28 L29 L30 L31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 against normal blind 1 named "d254_2"
chamfer "Chamfer4" distance 0.3 named "d264_5" Rotate Angle 75 named "d265_5"
rectangular_pattern "R-Pattern1" uSpaceDistance 1.02 named "d280_5" vSpaceDistance 0 named "d281_5"
face "EdgeFlange13" EdgeWidth_1 0.6 named "d282_5" EdgeWidth_2 1.5 named "d283_5" EdgeWidth_1 1.5 named "d284_2" EdgeWidth_2 0.6 named "d285_3" FlangeHeight 2.5 named "d286_1" FlangeAngle 85 named "d287_3" BendRemnant 0.3 named "d288_3"
face "EdgeFlange14" FlangeHeight 1.5 named "d289_3" FlangeAngle 10 named "d290_1"
sketch "Sketch2" plane through (0, 1.55, 0) normal (0, 1, 0) x axis (-1, 0, 0)
  line L1 (0.76, 7.4601) -> (0.76, 10.87)
  line L2 (0.26, 7.4601) -> (0.76, 7.4601)
  line L3 (0.26, 10.87) -> (0.26, 7.4601)
  line L4 (-0.26, 10.87) -> (0.26, 10.87)
  line L5 (-0.26, 7.4601) -> (-0.26, 10.87)
  line L6 (-0.76, 7.4601) -> (-0.26, 7.4601)
  line L7 (-0.76, 10.87) -> (-0.76, 7.4601)
  line L8 (-1.28, 10.87) -> (-0.76, 10.87)
  line L9 (-1.28, 7.4601) -> (-1.28, 10.87)
  line L10 (-1.78, 7.4601) -> (-1.28, 7.4601)
  line L11 (-1.78, 10.87) -> (-1.78, 7.4601)
  line L12 (-2.3, 10.87) -> (-1.78, 10.87)
  line L13 (-2.3, 7.4601) -> (-2.3, 10.87)
  line L14 (-2.8, 7.4601) -> (-2.3, 7.4601)
  line L15 (-2.8, 10.87) -> (-2.8, 7.4601)
  line L16 (-3.32, 10.87) -> (-2.8, 10.87)
  line L17 (-3.32, 7.4601) -> (-3.32, 10.87)
  line L18 (-3.82, 7.4601) -> (-3.32, 7.4601)
  line L19 (-3.82, 10.87) -> (-3.82, 7.4601)
  line L20 (-5.75, 10.87) -> (-3.82, 10.87)
  line L21 (-5.75, 11.77) -> (-5.75, 10.87)
  line L22 (-6.75, 11.77) -> (-5.75, 11.77)
  line L23 (-6.75, 12.67) -> (-6.75, 11.77)
  line L24 (-6.95, 12.67) -> (-6.75, 12.67)
  line L25 (-6.95, 0.37) -> (-6.95, 0.87)
  line L26 (-6.0906, 0.37) -> (-6.95, 0.37)
  line L27 (-5.3394, 0.37) -> (-6.0906, 0.37)
  line L28 (5.3394, 0.37) -> (-5.3394, 0.37)
  line L29 (6.0906, 0.37) -> (5.3394, 0.37)
  line L30 (6.95, 0.37) -> (6.0906, 0.37)
  line L31 (6.95, 0.87) -> (6.95, 0.37)
  line L32 (6.75, 12.67) -> (6.95, 12.67)
  line L33 (6.75, 11.77) -> (6.75, 12.67)
  line L34 (5.75, 11.77) -> (6.75, 11.77)
  line L35 (5.75, 10.87) -> (5.75, 11.77)
  line L36 (3.82, 10.87) -> (5.75, 10.87)
  line L37 (3.82, 7.4601) -> (3.82, 10.87)
  line L38 (3.32, 7.4601) -> (3.82, 7.4601)
  line L39 (3.32, 10.87) -> (3.32, 7.4601)
  line L40 (2.8, 10.87) -> (3.32, 10.87)
  line L41 (2.8, 7.4601) -> (2.8, 10.87)
  line L42 (2.3, 7.4601) -> (2.8, 7.4601)
  line L43 (2.3, 10.87) -> (2.3, 7.4601)
  line L44 (1.78, 10.87) -> (2.3, 10.87)
  line L45 (1.78, 7.4601) -> (1.78, 10.87)
  line L46
  line L47 (1.28, 10.87) -> (1.28, 7.4601)
  line L48 (0.76, 10.87) -> (1.28, 10.87)
  line L49 (6.73, 12.64) -> (-6.73, 12.64)
  line L50 (6.73, 11.79) -> (6.73, 12.64)
  line L51 (5.77, 11.79) -> (6.73, 11.79)
  line L52 (5.77, 10.89) -> (5.77, 11.79)
  line L53 (-5.77, 10.89) -> (5.77, 10.89)
  line L54 (-5.77, 11.79) -> (-5.77, 10.89)
  line L55 (-6.73, 11.79) -> (-5.77, 11.79)
  line L56 (-6.73, 12.64) -> (-6.73, 11.79)
  line L57 (0, 14.5261) -> (0, 0)
  line L58 (-3.845, 10.89) -> (-3.845, 12.64)
  line L59 (-3.295, 11.39) -> (-3.845, 11.39)
  line L60 (-3.295, 12.64) -> (-3.295, 10.89)
  line L61 (-2.825, 10.89) -> (-2.825, 12.64)
  line L62 (-2.275, 12.64) -> (-2.275, 10.89)
  line L63 (-2.275, 11.39) -> (-2.825, 11.39)
  line L64 (-1.805, 10.89) -> (-1.805, 12.64)
  line L65 (-1.255, 12.64) -> (-1.255, 10.89)
  line L66 (-1.255, 11.39) -> (-1.805, 11.39)
  line L67 (-0.785, 10.89) -> (-0.785, 12.64)
  line L68 (-0.235, 12.64) -> (-0.235, 10.89)
  line L69 (-0.235, 11.39) -> (-0.785, 11.39)
  line L70 (0.235, 10.89) -> (0.235, 12.64)
  line L71 (0.785, 12.64) -> (0.785, 10.89)
  line L72 (0.785, 11.39) -> (0.235, 11.39)
  line L73 (1.255, 10.89) -> (1.255, 12.64)
  line L74 (1.805, 12.64) -> (1.805, 10.89)
  line L75 (1.805, 11.39) -> (1.255, 11.39)
  line L76 (2.275, 10.89) -> (2.275, 12.64)
  line L77 (2.825, 12.64) -> (2.825, 10.89)
  line L78 (2.825, 11.39) -> (2.275, 11.39)
  line L79 (3.295, 10.89) -> (3.295, 12.64)
  line L80 (3.845, 12.64) -> (3.845, 10.89)
  line L81 (3.845, 11.39) -> (3.295, 11.39)
  line L82 (-6.95, 1.37) -> (-6.95, 12.67)
  line L83 (-6.45, 1.37) -> (-6.95, 1.37)
  line L84 (-6.45, 0.87) -> (-6.45, 1.37)
  line L85 (-6.95, 0.87) -> (-6.45, 0.87)
  line L86 (6.45, 0.87) -> (6.95, 0.87)
  line L87 (6.45, 1.37) -> (6.45, 0.87)
  line L88 (6.95, 1.37) -> (6.45, 1.37)
  line L89 (6.95, 12.67) -> (6.95, 1.37)
  point P1 (0, 0)
  point P58 (0, 0)
  point P54 (5.77, 10.89)
  point P55 (-5.77, 10.89)
  point P53 (5.77, 11.79)
  point P56 (-5.77, 11.79)
  point P50 (-6.73, 12.64)
  point P51 (6.73, 12.64)
  point P60 (-3.845, 12.64)
  point P63 (-3.295, 12.64)
  point P64 (-3.57, 11.39)
  point P65 (-3.845, 10.89)
  point P61 (-3.845, 11.39)
  point P66 (-3.295, 10.89)
  point P62 (-3.295, 11.39)
  horizontal L49
  vertical L50
  horizontal L51
  vertical L52
  horizontal L53
  vertical L56
  horizontal L55
  vertical L54
  coincident P1 P58
  vertical L57
  symmetric P54 P55 L57
  symmetric P53 P56 L57
  symmetric P50 P51 L57
  coincident L49 P60
  perpendicular L49 L58
  perpendicular L58 L59
  coincident L49 P63
  perpendicular L49 L60
  midpoint L59 P64
  coincident L53 P65
  coincident P61 L58
  coincident L53 P66
  coincident P62 L60
  dimension "d294" distance L36 L53 = 0.02
  dimension "d295_3" distance L35 L52 = 0.02 (= "d294")
  dimension "d296_1" distance L34 L51 = 0.02 (= "d294")
  dimension "d297_1" distance L33 L50 = 0.02 (= "d294")
  dimension "d298_3" distance L49 L53 = 1.75
  dimension "d317_3" distance L58 L60 = 0.55
  dimension "d318_1" distance L49 L59 = 1.25
  dimension "d319_3" distance L57 P64 = 3.57 (= "( ( 8 - 1 ) * 1.02 / 2 ) * 1 mm")
  dimension "d328_3" R-Pattern1-uDistance = 1.02
  dimension "d329_3" R-Pattern1-vDistance = 0
extrude "Extrude2" new body sketch "Sketch2" profile of L49 L50 L51 L52 L53 L54 L55 L56 L58 L59 L60 L61 L62 L63 L64 L65 L66 L67 L68 L69 L70 L71 L72 L73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 against normal blind 10 named "d299_3"
work_plane "WorkPlane1" AlongDistance 1 named "d303_3"
sketch "Sketch1" plane through (0, 2.55, 6.52) normal (0, 1, 0) x axis (1, 0, 0)
  line L1 (5.75, -5.75) -> (-5.75, -5.75)
  line L2 (5.75, 5.75) -> (5.75, -5.75)
  line L3 (-5.75, 5.75) -> (5.75, 5.75)
  line L4 (-5.75, -5.75) -> (-5.75, 5.75)
  line L5 (5.75, 5.75) -> (-5.75, -5.75)
  line L6 (-5.75, 5.75) -> (5.75, -5.75)
  line L7 (10.5059, 0) -> (0, 0)
  circle C1 centre (3.57, -5.125) radius 0.375
  circle C2 centre (2.55, -5.125) radius 0.375
  circle C3 centre (1.53, -5.125) radius 0.375
  circle C4 centre (0.51, -5.125) radius 0.375
  circle C5 centre (-0.51, -5.125) radius 0.375
  circle C6 centre (-1.53, -5.125) radius 0.375
  circle C7 centre (-2.55, -5.125) radius 0.375
  circle C8 centre (-3.57, -5.125) radius 0.375
  circle C9 centre (4.445, 5) radius 0.3845
  circle C10 centre (3.175, 5) radius 0.3845
  circle C11 centre (1.905, 5) radius 0.3845
  circle C12 centre (0.635, 5) radius 0.3845
  circle C13 centre (-0.635, 5) radius 0.3845
  circle C14 centre (-1.905, 5) radius 0.3845
  circle C15 centre (-3.175, 5) radius 0.3845
  circle C16 centre (-4.445, 5) radius 0.3845
  point P6 (0, 0)
  point P1 (0, 0)
  point P15 (0, 0)
  point P7 (3.57, -5.125)
  point P17 (4.445, 5)
  perpendicular L1 L2
  parallel L1 L3
  parallel L2 L4
  horizontal L1
  coincident L5 P6
  coincident L6 P6
  coincident P1 P6
  coincident P1 P15
  horizontal L7
  dimension "d304_3" distance L1 L3 = 11.5
  dimension "d305_3" distance L2 L4 = 11.5
  dimension "d306_3" diameter C1 = 0.75
  dimension "d307_3" distance P1 P7 = 3.57 (= "( ( 8 - 1 ) * 1.02 / 2 ) * 1 mm")
  dimension "d308_3" distance P1 P7 = 5.125
  dimension "d378_2" distance P1 P17 = 4.445 (= "( ( 8 - 1 ) * 1.27 / 2 ) * 1 mm")
  dimension "d379_3" distance L7 P17 = 5
  dimension "d311_3" R-Pattern1-uDistance = -1.02
  dimension "d312_3" R-Pattern1-vDistance = 0
  dimension "d376_2" R-Pattern2-uDistance = -1.27
  dimension "d377_2" R-Pattern2-vDistance = 0
extrude "Extrude1" new body sketch "Sketch1" profile of L1 L2 L3 L4 C1 C2 C3 C4 C5 C6 C7 C8 C9 C10 C11 C12 C13 C14 C15 C16 along normal blind 1 named "d313_3"
sketch "Sketch2" plane through (0, 3.55, 0) normal (0, 1, 0) x axis (-1, 0, 0)
  line L1 (5.75, 12.27) -> (5.75, 0.77)
  line L2 (-5.75, 12.27) -> (5.75, 12.27)
  line L3 (-5.75, 0.77) -> (-5.75, 12.27)
  line L4 (5.75, 0.77) -> (-5.75, 0.77)
  line L5 (-5.75, 3.02) -> (5.75, 3.02)
  line L6 (-5.75, 10.02) -> (-5.75, 3.02)
  line L7 (5.75, 10.02) -> (-5.75, 10.02)
  line L8 (5.75, 3.02) -> (5.75, 10.02)
  line L9 (-5.75, 10.02) -> (5.75, 3.02)
  line L10 (5.75, 10.02) -> (-5.75, 3.02)
  circle C1 centre (-4.445, 1.52) radius 0.3845
  circle C2 centre (3.57, 11.645) radius 0.375
  circle C3 centre (2.55, 11.645) radius 0.375
  circle C4 centre (1.53, 11.645) radius 0.375
  circle C5 centre (0.51, 11.645) radius 0.375
  circle C6 centre (-0.51, 11.645) radius 0.375
  circle C7 centre (-1.53, 11.645) radius 0.375
  circle C8 centre (-2.55, 11.645) radius 0.375
  circle C9 centre (-3.57, 11.645) radius 0.375
  circle C10 centre (1.905, 1.52) radius 0.3845
  circle C11 centre (3.175, 1.52) radius 0.3845
  circle C12 centre (4.445, 1.52) radius 0.3845
  circle C13 centre (-1.905, 1.52) radius 0.3845
  circle C14 centre (-0.635, 1.52) radius 0.3845
  circle C15 centre (-3.175, 1.52) radius 0.3845
  circle C16 centre (0.635, 1.52) radius 0.3845
  point P19 (0, 6.52)
  point P1 (0, 0)
  point P20 (5.75, 6.52)
  perpendicular L5 L6
  parallel L5 L7
  parallel L6 L8
  horizontal L5
  coincident L9 P19
  coincident L10 P19
  vertical P1 P19
  midpoint L1 P20
  horizontal P19 P20
  dimension "d315_1" distance L5 L7 = 7
  dimension "d316_3" distance L6 L8 = 11.5
extrude "Extrude2" new body sketch "Sketch2" profile of L1 L3 L5 L6 L7 L8 along normal blind 5.5 named "d324_1"
extrude "Extrude3" sketch "Sketch2" profile of L53 L58 L59 L60 L61 L62 L63 L64 L65 L66 L67 L68 L69 L70 L71 L72 L73 L74 L75 L76 L77 L78 L79 L80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 blind 2 named "d331_3"
fillet "Fillet1" radius 0.2 named "d333_1"
sketch "Sketch9" plane through (7.95, 0, 0) normal (1, 0, 0) x axis (0, 1, 0)
  line L1 (2.1927, 0.399) -> (-1.875, 0.399)
  line L2 (2.525, -2.075) -> (2.525, 0.249)
  line L3 (3.875, 0.4) -> (3.875, -2.075)
  line L4 (5.05, 0.4) -> (3.875, 0.4)
  line L5 (5.05, 1.75) -> (5.05, 0.4)
  line L6 (5.9879, 1.75) -> (5.05, 1.75)
  line L7 (5.9879, 10.3) -> (5.9879, 1.75)
  line L8 (0.9, 10.3) -> (5.9879, 10.3)
  line L9 (-2.1, 13.3) -> (0.9, 10.3)
  line L10 (-10.45, 13.3) -> (-2.1, 13.3)
  line L11 (-10.45, 0.4) -> (-10.45, 13.3)
  line L12 (-1.875, 0.4) -> (-10.45, 0.4)
  line L13 (-1.875, 0.399) -> (-1.875, 0.4)
  line L14 (3.5, 0.4) -> (3.5, -2.075)
  line L15 (2.9, -2.075) -> (2.9, 0.4)
  line L16 (3.2, 0.4) -> (3.2, -2.075)
  arc A1 centre (2.325, 0.249) radius 0.2 clockwise from (2.1927, 0.399) to (2.525, 0.249)
  arc A2 centre (3.2, -2.075) radius 0.675 clockwise from (3.875, -2.075) to (2.525, -2.075)
  arc A3 centre (3.2, 0.4) radius 0.3 clockwise from (2.9, 0.4) to (3.5, 0.4)
  arc A4 centre (3.2, -2.075) radius 0.3 clockwise from (3.5, -2.075) to (2.9, -2.075)
  point P8 (3.2, -2.075)
  point P23 (3.2, -2.075)
  point P24 (3.2, 0.4)
  tangent L14 A3
  tangent A3 L15
  parallel L14 L15
  tangent L15 A4
  tangent L14 A4
  coincident P8 P23
  vertical L16
  coincident L4 P24
  dimension "d336_3" radius A3 = 0.3
extrude "Extrude8" cut sketch "Sketch9" profile of L14 A3 L15 A4 no distance stored
sketch "Sketch10" plane through (0, 0, 0) normal (0, 0, 1) x axis (1, 0, 0)
  line L1 (7.95, 2.9) -> (7.8, 2.9)
  line L2 (7.8, 2.9) -> (7.95, 2.9)
  line L3 (7.95, 3.5) -> (7.8, 3.5)
  line L4 (7.8, 3.5) -> (7.95, 3.5)
  line L5 (7.95, 3.5) -> (7.95, 2.9)
  line L6 (8.3116, 3.2) -> (7.95, 3.2)
  line L7 (7.95, 3.1165) -> (7.95, 3.2)
  line L8 (7.9125, 3.0516) -> (7.875, 3.0299)
  line L9 (8.1, 3.0732) -> (8.1, 3.2)
  line L10 (7.95, 2.9) -> (8.025, 2.9433)
  arc A1 centre (7.95, 3.0732) radius 0.15 clockwise from (8.1, 3.0732) to (8.025, 2.9433)
  arc A2 centre (7.875, 3.1165) radius 0.075 clockwise from (7.95, 3.1165) to (7.9125, 3.0516)
  arc A3 centre (7.95, 2.9) radius 0.15 clockwise from (7.8, 2.9) to (7.875, 3.0299)
  point P3 (7.95, 2.9)
  point P6 (7.95, 2.9)
  point P5 (7.95, 3.5)
  point P7 (7.95, 3.5)
  point P8 (7.95, 3.2)
  point P10 (7.95, 3.1165)
  point P13 (8.1, 3.2)
  point P17 (7.95, 2.9)
  point P2 (7.8, 2.9)
  point P19 (7.8, 2.9)
  point P20 (7.95, 2.9)
  coincident P3 P6
  coincident P5 P7
  midpoint L5 P8
  horizontal L6
  coincident L5 P10
  perpendicular L6 L7
  coincident L6 P13
  perpendicular L6 L9
  tangent L9 A1
  tangent A1 L10
  coincident P6 P17
  parallel L8 L10
  tangent L8 A2
  tangent L7 A2
  tangent L8 A3
  coincident P2 P19
  coincident L2 P20
  dimension "d339_3" angle L2 L8 = 30
  dimension "d343_3" distance P8 P13 = 0.15 (= "d1_5")
  dimension "d345_3" radius A1 = 0.15 (= "d1_5")
  dimension "d346_3" distance L8 L10 = 0.15 (= "d1_5")
  dimension "d347_3" radius A2 = 0.075
sweep "Sweep2" sketch "Sketch10" TwistAngle 0 named "d352_3" TaperAngle 0 named "d353_3"
sketch "Sketch11" plane through (0, 0, 0.099) normal (0, 0, -1) x axis (1, 0, 0)
  line L1 (7.65, 1.875) -> (7.65, -2.125)
  line L2 (6.95, 1.875) -> (7.65, 1.875)
  line L3 (6.95, -2.125) -> (6.95, 1.875)
  line L4 (7.65, -2.125) -> (6.95, -2.125)
  arc A1 centre (5.2715, 0) radius 2.2 clockwise from (6.95, 1.4222) to (6.95, -1.4222)
  point P7 (6.95, -1.4222)
  point P6 (6.95, 1.4222)
  point P1 (0, 0)
  point P8 (5.2715, 0)
  coincident L3 P7
  coincident L3 P6
  horizontal P1 P8
  dimension "d355_3" radius A1 = 2.2
extrude "Extrude9" cut sketch "Sketch11" profile of L3 A1 against normal blind 0.15 named "d356_3" (magnitude of "-d1_5")
mirror "Mirror3"
sketch "Sketch6" plane through (-7.8, 0, 0) normal (-1, 0, 0) x axis (0, -1, 0)
  line L1 (-5.8, 0.37) -> (-5.8, 13.37)
  line L2 (10.45, 0.37) -> (-5.8, 0.37)
  line L3 (10.45, 13.37) -> (10.45, 0.37)
  line L4 (-5.8, 13.37) -> (10.45, 13.37)
  line L5 (-1.05, 10.37) -> (-5.8, 10.37)
  line L6 (1.95, 13.37) -> (-1.05, 10.37)
  point P6 (-5.8, 10.37)
  point P8 (1.95, 13.37)
  coincident L1 P6
  coincident L4 P8
  horizontal L5
  dimension "d361_3" angle L5 L6 = 45
  dimension "d362_3" distance L3 P8 = 8.5
  dimension "d363_3" distance L4 L5 = 3
extrude "Extrude14" cut sketch "Sketch6" profile of L1 L4 L5 L6 against normal blind 0.15 named "d364_3"
mirror "Mirror1"
sketch "Sketch1" plane through (0, 0, 0) normal (1, 0, 0) x axis (0, 1, 0)
  line L1 (8.365, 1.695) -> (2.35, 1.695)
  line L2 (9.065, -3.35) -> (9.065, 0.995)
  line L3 (8.715, -3.35) -> (9.065, -3.35)
  line L4 (8.715, 0.995) -> (8.715, -3.35)
  line L5 (2.35, 1.345) -> (8.365, 1.345)
  line L6 (2.35, 1.695) -> (2.35, 1.345)
  line L7 (2.55, 1.52) -> (2.35, 1.52)
  line L8 (6.525, -3.35) -> (6.525, 0.995)
  line L9 (6.175, -3.35) -> (6.525, -3.35)
  line L10 (6.175, 0.995) -> (6.175, -3.35)
  arc A1 centre (8.365, 0.995) radius 0.7 clockwise from (8.365, 1.695) to (9.065, 0.995)
  arc A2 centre (8.365, 0.995) radius 0.35 clockwise from (8.365, 1.345) to (8.715, 0.995)
  arc A3 centre (5.825, 0.995) radius 0.7 clockwise from (5.825, 1.695) to (6.525, 0.995)
  arc A4 centre (5.825, 0.995) radius 0.35 clockwise from (5.825, 1.345) to (6.175, 0.995)
  point P12 (2.35, 1.52)
  point P14 (8.89, -3.35)
  point P15 (5.825, 1.695)
  point P18 (5.825, 1.345)
  point P23 (6.35, -3.35)
  point P13 (2.55, 1.52)
  point P24 (2.55, 1.52)
  point P1 (0, 0)
  point P6 (9.065, -3.35)
  tangent L1 A1
  tangent A1 L2
  tangent L4 A2
  vertical L6
  horizontal L5
  horizontal L1
  vertical L2
  vertical L4
  horizontal L3
  tangent A2 L5
  concentric A1 A2
  midpoint L6 P12
  horizontal L7
  midpoint L3 P14
  tangent L1 A3
  coincident L1 P15
  tangent L5 A4
  coincident L5 P18
  tangent A3 L8
  tangent A4 L10
  vertical L10
  horizontal L9
  vertical L8
  equal A1 A3
  concentric A3 A4
  midpoint L9 P23
  collinear L3 L9
  coincident P13 P24
  dimension "d367_3" distance L2 L4 = 0.35
  dimension "d368_3" distance P1 P14 = 8.89
  dimension "d370_2" radius A1 = 0.7
  dimension "d371" distance L8 L10 = 0.35 (= "d367_3")
  dimension "d372_2" distance P14 P23 = 2.54
  dimension "d373_2" distance P1 P6 = 3.35 (= "3.5 mm - d1_5")
  dimension "d380_3" distance L6 P13 = 0.2
extrude "Extrude1" new body sketch "Sketch1" profile of L1 A1 L2 L3 L4 A2 L5 L6 A3 distance 0.5 named "d382_2" from offset 4.445 (= "( ( 8 - 1 ) * 1.27 / 2 ) * 1 mm") named "d381_3"
extrude "Extrude2" new body sketch "Sketch1" profile of L1 L5 L6 A3 A4 L8 L9 L10 distance 0.5 named "d385_2" from offset 3.175 (= "( ( ( 8 - 1 ) / 2 - 1 ) * 1.27 ) * 1 mm") named "d384_2"
rectangular_pattern "R-Pattern1" uSpaceDistance -2.54 (= "( -1.27 * 2 ) * 1 mm") named "d389_1" vSpaceDistance 0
